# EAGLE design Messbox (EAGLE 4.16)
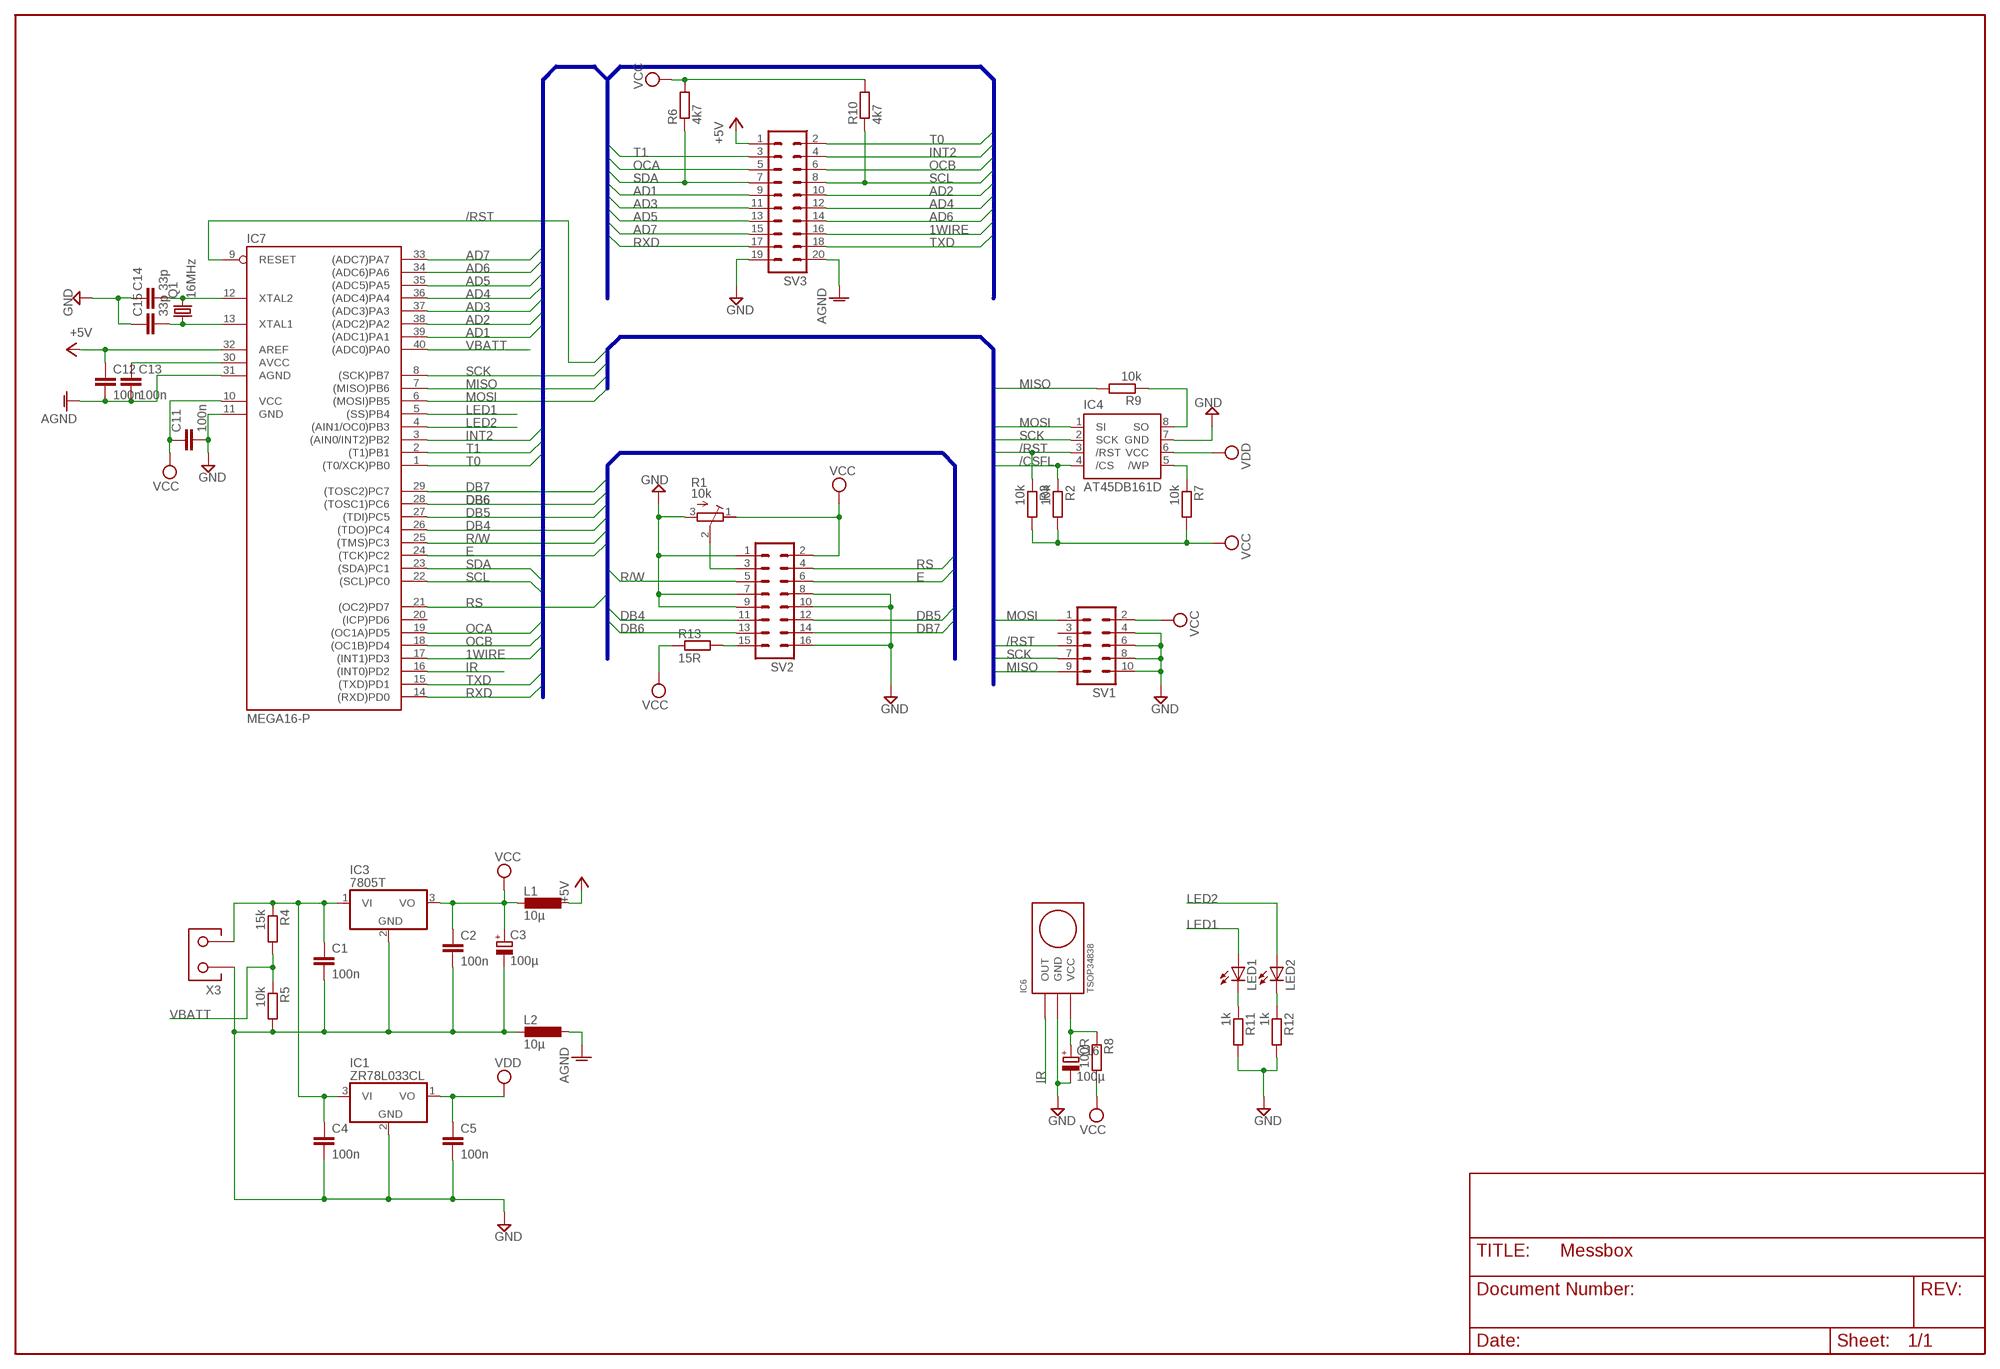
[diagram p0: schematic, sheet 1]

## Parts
C1  100n  C-EUC1206K  [C1206K]
C2  100n  C-EUC1206K  [C1206K]
C3  100µ  CPOL-EUE2.5-6  [E2,5-6]
C4  100n  C-EUC1206K  [C1206K]
C5  100n  C-EUC1206K  [C1206K]
C11  100n  C-EUC1206K  [C1206K]
C12  100n  C-EUC1206K  [C1206K]
C13  100n  C-EUC1206K  [C1206K]
C14  33p  C-EUC1206K  [C1206K]
C15  33p  C-EUC1206K  [C1206K]
C16  100µ  CPOL-EUE2.5-6  [E2,5-6]
IC1  ZR78L033CL  [TO92]
IC3  7805T  [TO220H]
IC4  AT45DB161D  [SOIC8]
IC6  TSOP34838  [TSOP348]
IC7  MEGA16-P  [DIL40]
L1  10µ  L-EU0207/12  [0207/12]
L2  10µ  L-EU0207/12  [0207/12]
LED1  LED5MM  [LED5MM]
LED2  LED5MM  [LED5MM]
Q1  16MHz  CRYTALHC49U-V  [HC49U-V]
R1  10k  R-TRIMMT93YB  [RTRIMT93YB]
R2  10k  R-EU_0207/10  [0207/10]
R3  10k  R-EU_0207/10  [0207/10]
R4  15k  R-EU_0207/10  [0207/10]
R5  10k  R-EU_0207/10  [0207/10]
R6  4k7  R-EU_0207/10  [0207/10]
R7  10k  R-EU_0207/10  [0207/10]
R8  100R  R-EU_0207/10  [0207/10]
R9  10k  R-EU_0207/10  [0207/10]
R10  4k7  R-EU_0207/10  [0207/10]
R11  1k  R-EU_0207/10  [0207/10]
R12  1k  R-EU_0207/10  [0207/10]
R13  15R  R-EU_0207/10  [0207/10]
SV1  ML10  [ML10]
SV2  ML16  [ML16]
SV3  ML20  [ML20]
X3  AKL-2_3,5  [AKL-2_3,5]

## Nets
1WIRE: IC7.17((INT1)PD3) SV3.16
+5V: C12.1 IC7.32(AREF) L1.1 SV3.1
/CSFL: IC4.4(/CS) R2.1
/RST: IC4.3(/RST) IC7.9(RESET) R3.1 SV1.5
AD1: IC7.39((ADC1)PA1) SV3.9
AD2: IC7.38((ADC2)PA2) SV3.10
AD3: IC7.37((ADC3)PA3) SV3.11
AD4: IC7.36((ADC4)PA4) SV3.12
AD5: IC7.35((ADC5)PA5) SV3.13
AD6: IC7.34((ADC6)PA6) SV3.14
AD7: IC7.33((ADC7)PA7) SV3.15
AGND: C12.2 C13.2 IC7.31(AGND) L2.1 SV3.20
DB4: IC7.26((TDO)PC4) SV2.11
DB5: IC7.27((TDI)PC5) SV2.12
DB6: IC7.28((TOSC1)PC6) SV2.13
DB7: IC7.29((TOSC2)PC7) SV2.14
E: IC7.24((TCK)PC2) SV2.6
GND: C1.2 C2.2 C3.- C4.2 C5.2 C11.2 C14.1 C15.1 C16.- IC1.2(GND) IC3.2(GND) IC4.7(GND) IC6.P$2(GND) IC7.11(GND) L2.2 R1.3(E) R5.2 R11.2 R12.2 SV1.4 SV1.6 SV1.8 SV1.10 SV2.1 SV2.7 SV2.8 SV2.9 SV2.10 SV2.16 SV3.19 X3.P$1
INT2: IC7.3((AIN0/INT2)PB2) SV3.4
IR: IC6.P$1(OUT) IC7.16((INT0)PD2)
LED1: IC7.5((SS)PB4) LED1.A
LED2: IC7.4((AIN1/OC0)PB3) LED2.A
MISO: IC7.7((MISO)PB6) R9.2 SV1.9
MOSI: IC4.1(SI) IC7.6((MOSI)PB5) SV1.1
N$1: LED2.K(C) R12.1
N$2: R13.2 SV2.15
N$3: LED1.K(C) R11.1
N$4: R1.2(S) SV2.3
N$14: IC4.8(SO) R9.1
N$18: C16.+ IC6.P$3(VCC) R8.1
N$20: C1.1 C4.1 IC1.3(VI) IC3.1(VI) R4.1 X3.P$2
N$21: C15.2 IC7.13(XTAL1) Q1.1
N$23: C14.2 IC7.12(XTAL2) Q1.2
N$42: IC4.5(/WP) R7.1
N$46: C13.1 IC7.30(AVCC)
OCA: IC7.19((OC1A)PD5) SV3.5
OCB: IC7.18((OC1B)PD4) SV3.6
R/W: IC7.25((TMS)PC3) SV2.5
RS: IC7.21((OC2)PD7) SV2.4
RXD: IC7.14((RXD)PD0) SV3.17
SCK: IC4.2(SCK) IC7.8((SCK)PB7) SV1.7
SCL: IC7.22((SCL)PC0) R10.1 SV3.8
SDA: IC7.23((SDA)PC1) R6.1 SV3.7
T0: IC7.1((T0/XCK)PB0) SV3.2
T1: IC7.2((T1)PB1) SV3.3
TXD: IC7.15((TXD)PD1) SV3.18
VBATT: IC7.40((ADC0)PA0) R4.2 R5.1
VCC: C2.1 C3.+ C11.1 IC3.3(VO) IC7.10(VCC) L1.2 R1.1(A) R2.2 R3.2 R6.2 R7.2 R8.2 R10.2 R13.1 SV1.2 SV2.2
VDD: C5.1 IC1.1(VO) IC4.6(VCC)
Unconnected: IC7.20((ICP)PD6) SV1.3

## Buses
MOSI,MISO,SCK,/RST,/CSFL
RS,R/W,E,DB[4..7]
AD[0..7],OCA,OCB,RXD,TXD,SDA,SCL,1WIRE,T0,T1,INT2

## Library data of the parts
C1 C2 C4 C5 C11-C15 = rcl:C-EU: CAPACITOR, European symbol
C3 C16 = rcl:CPOL-EU: POLARIZED CAPACITOR, European symbol
IC1 = 0mylib:ZR78L033C: Positive VOLTAGE REGULATOR Source: http://cache.national.com/ds/LM/LM78L05.pdf http://www.fairchildsemi.com/ds/LM/LM7805.pdf
IC3 = linear:78*: Positive VOLTAGE REGULATOR
IC4 = 0mylib:AT45DB161D
IC6 = 0mylib:TSOP34838
IC7 = avr:MEGA16-P: MICROCONTROLLER 16 Kbytes FLASH 1 kbytes SRAM 512 bytes EEPROM USART 8-channel 10 bit ADC
L1 L2 = rcl:L-EU: INDUCTOR, European symbol
LED1 LED2 = led:LED: LED
Q1 = crystal:CRYTAL: CRYSTAL
R1 = rcl:R-TRIMM: Trimm resistor
R2-R13 = rcl:R-EU_: RESISTOR, European symbol
SV1 = con-harting-ml:ML10: HARTING
SV2 = con-harting-ml:ML16: HARTING
SV3 = con-harting-ml:ML20: HARTING
X3 = 0mylib:AKL-2_3,5

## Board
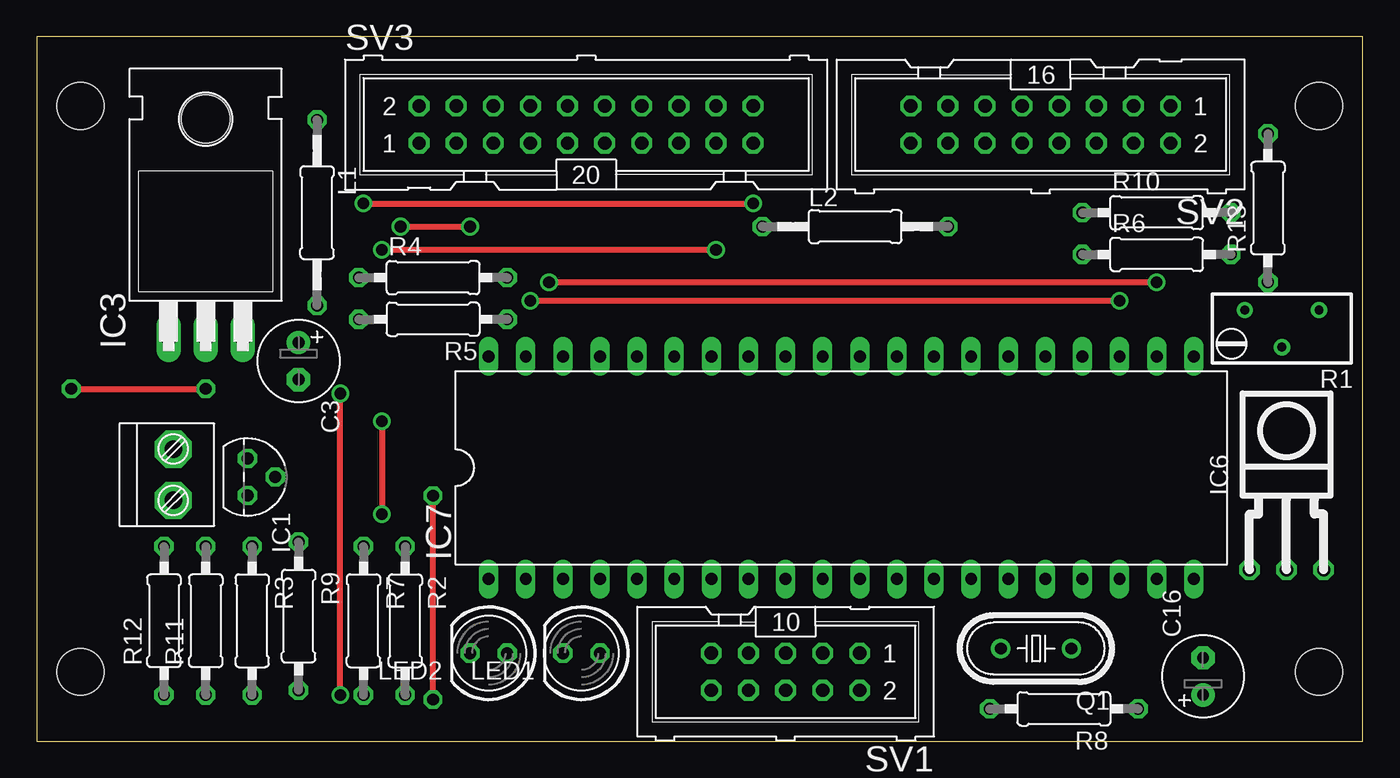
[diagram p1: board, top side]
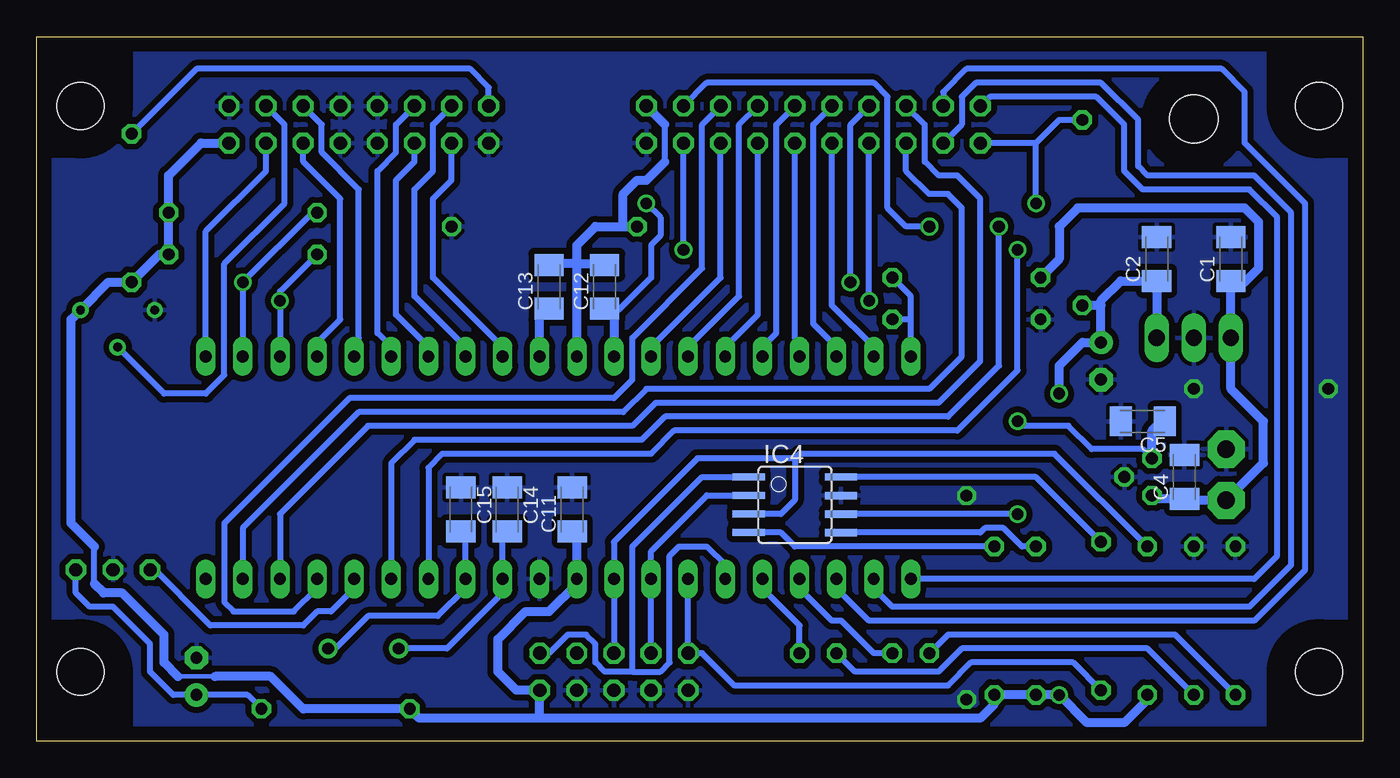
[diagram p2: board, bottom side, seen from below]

Size 90.79 x 48.25 mm. Coordinates in mm from the lower left corner, seen from the top.
Outline: 0,0 90.79,0 90.79,48.25 0,48.25 0,0
Copper layers (1*16): Top 0.035mm / dielectric 1.5mm / Bottom 0.035mm
Design rules "default": minimum track width 10mil, minimum drill 24mil, track to track 12mil, track to pad 12mil, pad to pad 12mil, via to via 12mil, smd to smd 12mil, copper to edge 40mil, drill to drill 8mil, minimum pad ring 10mil, minimum via ring 8mil, stop-mask expansion 4mil, vias tented up to drill 0mil, thermal gap 10mil
Holes 3.2 mm at 87.78,4.76 3.01,43.49 87.78,43.49 3.01,4.76
bRestrict: area -0.2,40.3 to 6.2,46.7; area -0.2,1.6 to 6.2,7.9; area 84.6,1.6 to 91,7.9; area 84.6,40.3 to 91,46.7; area 8.4,39.4 to 14.8,45.7; area -0.2,40.3 to 3,46.7; area -0.2,43.5 to 6.2,47.6; area -0.2,0.9 to 6.2,4.8; area -0.2,1.6 to 3,7.9; area 87.8,1.6 to 91,7.9; area 84.6,0.9 to 91,4.8; area 84.6,43.5 to 91,47.3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

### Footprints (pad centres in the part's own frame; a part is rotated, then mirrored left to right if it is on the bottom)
C1206K = smd 1.5 x 2: 1 -1.5,0; 2 1.5,0
E2,5-6 = drill 0.813 pad 1.6 round: + -1.27,0 | drill 0.813 pad 1.6 octagon: - 1.27,0
TO92 = drill 0.813 octagon: 1 -1.27,0; 2 0,1.905; 3 1.27,0
TO220H = drill 1.118 long: 1 -2.54,-10.16; 2 0,-10.16; 3 2.54,-10.16 | hole 3.302: 0,4.826
SOIC8 = smd 0.5 x 2.2: 1 -1.905,-3.154; 2 -0.645,-3.154; 3 0.625,-3.154; 4 1.895,-3.154; 5 1.905,3.154; 6 0.635,3.154; 7 -0.635,3.154; 8 -1.905,3.154
TSOP348 = drill 0.9 octagon: P$1 -5.08,2.54; P$2 -5.08,0; P$3 -5.08,-2.54
DIL40 = drill 0.813 long: 1 -24.13,-7.62; 2 -21.59,-7.62; 3 -19.05,-7.62; 4 -16.51,-7.62; 5 -13.97,-7.62; 6 -11.43,-7.62; 7 -8.89,-7.62; 8 -6.35,-7.62; 9 -3.81,-7.62; 10 -1.27,-7.62; 11 1.27,-7.62; 12 3.81,-7.62; 13 6.35,-7.62; 14 8.89,-7.62; 15 11.43,-7.62; 16 13.97,-7.62; 17 16.51,-7.62; 18 19.05,-7.62; 19 21.59,-7.62; 20 24.13,-7.62; 21 24.13,7.62; 22 21.59,7.62; 23 19.05,7.62; 24 16.51,7.62; 25 13.97,7.62; 26 11.43,7.62; 27 8.89,7.62; 28 6.35,7.62; 29 3.81,7.62; 30 1.27,7.62; 31 -1.27,7.62; 32 -3.81,7.62; 33 -6.35,7.62; 34 -8.89,7.62; 35 -11.43,7.62; 36 -13.97,7.62; 37 -16.51,7.62; 38 -19.05,7.62; 39 -21.59,7.62; 40 -24.13,7.62
0207/12 = drill 0.813 octagon: 1 -6.35,0; 2 6.35,0
LED5MM = drill 0.813 octagon: A -1.27,0; K 1.27,0
HC49U-V = drill 0.813 round: 1 -2.413,0; 2 2.413,0
RTRIMT93YB = drill 0.61 round: 1 1.27,-2.54; 2 -1.27,0; 3 1.27,2.54
0207/10 = drill 0.813 octagon: 1 -5.08,0; 2 5.08,0
ML10 = drill 0.914 octagon: 1 -5.08,-1.27; 2 -5.08,1.27; 3 -2.54,-1.27; 4 -2.54,1.27; 5 0,-1.27; 6 0,1.27; 7 2.54,-1.27; 8 2.54,1.27; 9 5.08,-1.27; 10 5.08,1.27
ML16 = drill 0.914 octagon: 1 -8.89,-1.27; 2 -8.89,1.27; 3 -6.35,-1.27; 4 -6.35,1.27; 5 -3.81,-1.27; 6 -3.81,1.27; 7 -1.27,-1.27; 8 -1.27,1.27; 9 1.27,-1.27; 10 1.27,1.27; 11 3.81,-1.27; 12 3.81,1.27; 13 6.35,-1.27; 14 6.35,1.27; 15 8.89,-1.27; 16 8.89,1.27
ML20 = drill 0.914 octagon: 1 -11.43,-1.27; 2 -11.43,1.27; 3 -8.89,-1.27; 4 -8.89,1.27; 5 -6.35,-1.27; 6 -6.35,1.27; 7 -3.81,-1.27; 8 -3.81,1.27; 9 -1.27,-1.27; 10 -1.27,1.27; 11 1.27,-1.27; 12 1.27,1.27; 13 3.81,-1.27; 14 3.81,1.27; 15 6.35,-1.27; 16 6.35,1.27; 17 8.89,-1.27; 18 8.89,1.27; 19 11.43,-1.27; 20 11.43,1.27
AKL-2_3,5 = drill 1.2 pad 2.54 octagon: P$1 0,0; P$2 3.5,0

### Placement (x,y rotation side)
C1  9.04,33.02 90 bottom
C2  14.12,33.02 90 bottom
C3  17.93,26.03 270 top
C4  12.22,18.09 90 bottom
C5  15.08,21.9 180 bottom
C11  54.13,15.87 90 bottom
C12  51.91,31.11 90 bottom
C13  55.72,31.11 90 bottom
C14  58.57,15.87 270 bottom
C15  61.75,15.87 270 bottom
C16  79.84,4.44 90 top
IC1  14.44,18.09 270 top
IC3  11.58,37.78 0 top
IC4  38.89,16.19 270 bottom
IC6  85.56,16.82 90 top
IC7  55.08,18.73 0 top
L1  19.2,36.19 270 top
L2  56.03,35.24 0 top
LED1  37.3,6.03 180 top
LED2  30.95,6.03 180 top
Q1  68.41,6.34 180 top
R1  85.24,28.25 90 top
R2  25.23,8.25 270 top
R3  14.76,8.25 270 top
R4  27.14,31.75 0 top
R5  27.14,28.89 180 top
R6  76.67,33.33 0 top
R7  22.38,8.25 270 top
R8  70.32,2.22 180 top
R9  17.93,8.57 270 top
R10  76.67,36.19 0 top
R11  11.58,8.25 90 top
R12  8.73,8.25 90 top
R13  84.29,36.51 90 top
SV1  51.27,4.76 180 top
SV2  68.73,42.22 180 top
SV3  37.62,42.22 0 top
X3  9.36,20 270 top

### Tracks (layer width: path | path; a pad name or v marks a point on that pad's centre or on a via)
1WIRE
  Bottom 0.406: IC7.17 71.59,10.47 73.18,8.88 77.3,8.88 77.94,9.52 77.94,14.92 69.37,23.49 51.27,23.49 50,24.76 50,27.62 45.24,32.38 45.24,42.22 SV3.16
+5V  (via drill 0.8)
  Top 0.406: v22.38,36.82 v49.05,36.82
  Bottom 0.406: 51.27,28.98 C12.1 51.91,29.21 51.59,29.52 50.95,29.52 48.73,31.75 48.73,33.97 48.09,34.6 48.09,35.87 v49.05,36.82 | 22.38,40.95 20.79,42.54 L1.1 | 22.38,40.95 SV3.1 | v22.38,36.82 22.38,40.95
  Bottom 0.61: 51.27,28.98 IC7.32
/CSFL
  Bottom 0.406: IC4.4 39.85,14.29 38.89,13.33 R2.1
/RST
  Bottom 0.406: 38.89,19.36 45.55,19.36 51.27,13.65 IC7.9 SV1.5 | 38.89,19.36 38.89,16.51 39.84,15.55 42.06,15.55 IC4.3 | R3.1 21.11,19.68 38.57,19.68 38.89,19.36
AD1
  Bottom 0.406: IC7.39 33.49,26.98 36.35,29.84 SV3.9
AD2
  Bottom 0.406: IC7.38 36.03,26.98 37.62,28.57 37.62,42.22 SV3.10
AD3
  Bottom 0.406: IC7.37 38.57,27.3 38.89,27.62 SV3.11
AD4
  Bottom 0.406: IC7.36 41.11,26.98 40.16,27.94 40.16,42.22 SV3.12
AD5
  Bottom 0.406: IC7.35 43.65,26.98 41.43,29.21 SV3.13
AD6
  Bottom 0.406: IC7.34 46.19,26.98 42.7,30.48 42.7,42.22 SV3.14
AD7
  Bottom 0.406: IC7.33 48.73,26.98 43.97,31.75 SV3.15
AGND
  Bottom 0.406: 55.72,32.7 C13.2 | 51.99,32.7 C12.2 | 47.78,39.68 47.78,42.22
  Bottom 0.61: IC7.31 53.81,32.7 | 53.81,32.7 55.72,32.7 | 53.81,32.7 51.99,32.7 | 53.81,32.7 53.81,33.97 52.54,35.24 50.63,35.24 | 47.78,42.22 SV3.20 | 50.63,35.24 50.63,37.46 49.68,38.41 49.05,38.41 47.78,39.68 | 50.63,35.24 L2.1
DB4
  Bottom 0.406: SV2.11 66.19,42.22 66.19,40.32 67.46,39.05 67.46,27.94 66.51,26.98 IC7.26
DB5
  Bottom 0.406: IC7.27 63.97,26.98 66.19,29.21 66.19,38.41 64.92,39.68 SV2.12
DB6
  Bottom 0.406: SV2.13 63.65,42.22 63.65,39.05 64.92,37.78 64.92,30.48 61.43,26.98 IC7.28
DB7
  Bottom 0.406: SV2.14 62.38,38.41 63.65,37.14 63.65,31.75 58.89,26.98 IC7.29
E
  Bottom 0.406: IC7.24 71.59,27.3 70,28.89 70,37.14 72.54,39.68 SV2.6
GND  (via drill 0.8 pad 1.27)
  Top 0.406: v27.14,2.85 v27.14,16.82 | v2.38,24.12 v11.58,24.12
  pour Bottom (isolate 0.406): 0.15,48.25 90.32,48.25 90.32,-0.01 0.15,-0.01 0.15,38.41
INT2
  Bottom 0.406: IC7.3 36.03,10.47 33.81,8.25 7.46,8.25 3.96,11.74 3.96,36.82 8.09,40.95 8.09,44.45 9.68,46.03 27.14,46.03 28.73,44.45 SV3.4
IR
  Bottom 0.406: IC6.P$1 83.02,12.06 78.89,7.93 72.54,7.93 71.59,8.88 70.64,8.88 69.05,10.47 IC7.16
LED1
  Bottom 0.406: LED1.A 38.57,7.93 41.11,10.47 IC7.5
LED2
  Bottom 0.406: IC7.4 38.57,10.47 36.35,8.25 35.71,8.25 33.49,6.03 LED2.A
MISO
  Bottom 0.406: IC7.7 SV1.9 45.24,6.03 43.02,3.81 28.41,3.81 26.82,5.39 19.84,5.39 R9.2
MOSI
  Bottom 0.406: SV1.1 55.72,6.03 54.45,7.3 53.18,7.3 52.54,6.66 52.54,5.39 51.91,4.76 50,4.76 | IC7.6 43.65,12.06 44.92,13.33 46.83,13.33 47.46,12.69 47.46,5.39 48.09,4.76 50,4.76 | IC4.1 45.24,18.09 50,13.33 50,4.76
N$1
  Bottom 0.406: LED2.K 28.41,7.3 12.85,7.3 R12.1
N$2
  Bottom 0.406: R13.2 79.84,46.03 61.11,46.03 59.84,44.76 SV2.15
N$3
  Bottom 0.406: LED1.K 34.76,4.76 29.05,4.76 27.46,6.34 14.76,6.34 R11.1
N$4
  Bottom 0.406: SV2.3 73.81,42.22 73.81,36.82 77.94,32.7 77.94,25.08 79.21,23.81 82.07,23.81 R1.2
N$14
  Bottom 0.406: IC4.8 22.38,18.09 R9.1
N$18
  Bottom 0.406: R8.1 76.35,3.17 C16.+ 81.43,3.17 83.02,4.76 83.02,6.66 85.56,9.2 87.15,9.2 88.1,10.15 IC6.P$3
N$20
  Bottom 0.406: X3.P$2 | C4.1 12.22,16.51 12.21,16.5
  Bottom 0.61: X3.P$2 6.82,19.05 6.82,21.9 9.04,24.12 IC3.1 9.04,31.43 | X3.P$2 12.21,16.5 | C4.1 14.21,16.59 IC1.3 | 9.04,31.43 C1.1 | R4.1 20.79,33.02 20.79,35.24 19.52,36.51 8.09,36.51 7.14,35.55 7.14,32.38 8.09,31.43 9.04,31.43
N$21
  Bottom 0.406: C15.2 61.75,14.28 61.43,13.96 IC7.13 61.43,10.47 63.34,8.57 68.1,8.57 70.32,6.34 Q1.1
N$23
  Bottom 0.406: Q1.2 62.7,6.34 58.89,10.15 IC7.12 58.89,13.96 58.57,14.28 C14.2
N$42
  Bottom 0.406: IC4.5 26.19,14.28 25.87,14.6 24.6,14.6 23.33,13.33 R7.1
N$46
  Bottom 0.406: 56.35,28.98 C13.1
  Bottom 0.61: IC7.30 56.35,28.98
OCA
  Bottom 0.406: IC7.19 76.67,14.6 68.73,22.54 50.63,22.54 49.05,24.12 29.68,24.12 27.46,26.35 27.46,36.51 28.41,37.46 29.68,37.46 31.27,39.05 SV3.5
OCB
  Bottom 0.406: IC7.18 74.13,15.55 68.1,21.59 50,21.59 48.41,23.17 29.05,23.17 26.19,26.03 26.19,37.14 27.78,38.73 29.05,38.73 30,39.68 30,42.22 SV3.6
R/W
  Bottom 0.406: IC7.25 69.05,27.3 68.73,27.62 68.73,37.78 71.27,40.32 71.27,42.22 SV2.5
RS
  Bottom 0.406: 79.53,26.35 IC7.21 79.21,34.92 75.08,39.05 SV2.4
RXD  (via drill 0.8)
  Top 0.406: v23.65,33.65 v46.51,33.65
  Bottom 0.406: IC7.14 63.97,18.73 63.02,19.68 48.73,19.68 47.14,21.27 27.78,21.27 23.65,25.39 v23.65,33.65 | v46.51,33.65 SV3.17
SCK
  Bottom 0.406: SV1.7 IC7.8 48.73,13.01 44.91,16.83 IC4.2
SCL  (via drill 0.8)
  Top 0.406: v35.08,31.43 v76.67,31.43
  Bottom 0.406: IC7.22 v76.67,31.43 71.91,36.19 R10.1 | v35.08,31.43 35.08,42.22 SV3.8
SDA  (via drill 0.8)
  Top 0.406: v33.81,30.16 v74.13,30.16
  Bottom 0.406: IC7.23 v74.13,30.16 74.13,30.79 R6.1 | v33.81,30.16 SV3.7
T0
  Bottom 0.406: IC7.1 7.46,11.11 5.87,12.69 5.87,35.87 7.77,37.78 15.08,37.78 16.35,39.05 16.35,42.22 18.25,44.13 25.55,44.13 SV3.2
T1
  Bottom 0.406: SV3.3 27.46,42.22 27.46,44.13 26.51,45.08 17.93,45.08 15.39,42.54 15.39,39.36 14.76,38.73 7.46,38.73 4.92,36.19 4.92,12.06 7.77,9.2 32.22,9.2 33.49,10.47 IC7.2
TXD  (via drill 0.8)
  Top 0.406: v24.92,35.24 v29.68,35.24
  Bottom 0.406: IC7.15 66.51,19.05 64.92,20.63 49.37,20.63 47.78,22.22 28.41,22.22 24.92,25.71 v24.92,35.24 | v29.68,35.24 31.27,35.24 32.54,36.51 32.54,44.13 33.49,45.08 44.92,45.08 SV3.18
VBATT
  Bottom 0.406: IC7.40 30.95,28.89 | 30.95,28.89 30.95,30.48 R4.2 | 30.95,28.89 R5.1
VCC  (via drill 0.8)
  Top 0.406: v20.79,3.17 v20.79,23.81
  Bottom 0.305: 78.57,4.44 81.11,4.44
  Bottom 0.406: 53.81,10.79 IC7.10 | C11.1 54.13,14.28 53.81,13.96 | IC3.3 14.76,28.25 | 86.83,10.79 86.83,13.33
  Bottom 0.61: 56.35,1.58 26.19,1.58 25.23,2.54 R2.2 R7.2 v20.79,3.17 18.89,1.27 16.35,1.27 14.76,2.85 R3.2 | 53.81,10.79 55.72,8.88 57.3,8.88 59.21,6.98 59.21,4.76 57.94,3.49 SV1.2 56.35,1.58 | SV2.2 79.53,40.95 81.75,38.73 R10.2 R6.2 82.38,33.33 R13.1 85.88,31.43 R1.1 88.42,28.89 88.42,14.92 86.83,13.33 | IC7.10 53.81,13.96 | IC3.3 C2.1 16.57,31.52 17.93,30.16 17.93,29.84 | v20.79,23.81 20.79,25.71 19.2,27.3 C3.+ 17.93,29.84 | 56.35,1.58 64.6,1.58 R8.2 72.54,2.22 74.77,4.44 78.57,4.44 | 81.11,4.44 82.07,5.39 82.07,7.3 84.92,10.15 86.19,10.15 86.83,10.79 | 17.93,29.84 L1.2
VDD  (via drill 0.8)
  Top 0.406: v23.65,21.9 v23.65,15.55
  Bottom 0.406: 13.81,21.9 C5.1 | v23.65,15.55 IC4.6 | v23.65,21.9 23.33,21.59 20.16,21.59 18.57,20 15.08,20 IC1.1
  Bottom 0.61: IC1.1 14.44,21.27 13.81,21.9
